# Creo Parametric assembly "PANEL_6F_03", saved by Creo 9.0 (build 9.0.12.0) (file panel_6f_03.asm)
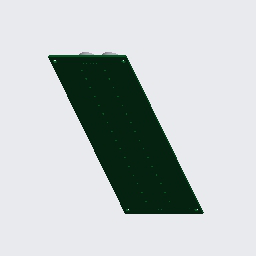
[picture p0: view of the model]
Units: millimeter Newton Second (mmNs); MM, TONNE, SECS

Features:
  1. coordinate system "PANEL_6F_03"
  2. imported feature "Import Feature id 4"
  3. component "PCB_6F"
  4. component "TX_6F_T1"
  5. component "TX_6F_T1"
  6. component "TX_6F_T1"
  7. component "TX_6F_T1"
  8. component "TX_6F_T1"
  9. component "TX_6F_T1"
  10. component "TX_6F_T1"
  11. component "TX_6F_T1"
  12. component "TX_6F_T1"
  13. component "TX_6F_T1"
  14. component "TX_6F_T1"
  15. component "TX_6F_T1"
  16. component "TX_6F_T1"
  17. component "TX_6F_T1"
  18. component "TX_6F_T1"
  19. component "TX_6F_T1"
